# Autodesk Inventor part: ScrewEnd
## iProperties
Created: 2005-11
Part Number: ScrewEnd
Document SubType Name: Modeling
Designer: Administrator
Manufacturer: Standard
Standards Organization: Custom
Author: Administrator
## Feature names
1. Extrusion1
2. Extrusion2
3. Hole1
4. Hole2
5. Chamfer1
6. Chamfer2
7. Chamfer3
8. Chamfer4
